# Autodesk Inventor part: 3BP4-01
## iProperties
Created: 2006-11
Part Number: 3BP4-01
Document SubType Name: Modeling
Designer: Darius
Author: Darius
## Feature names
1. Extrusion1
2. Hole1
3. Extrusion2
4. Mirror1
